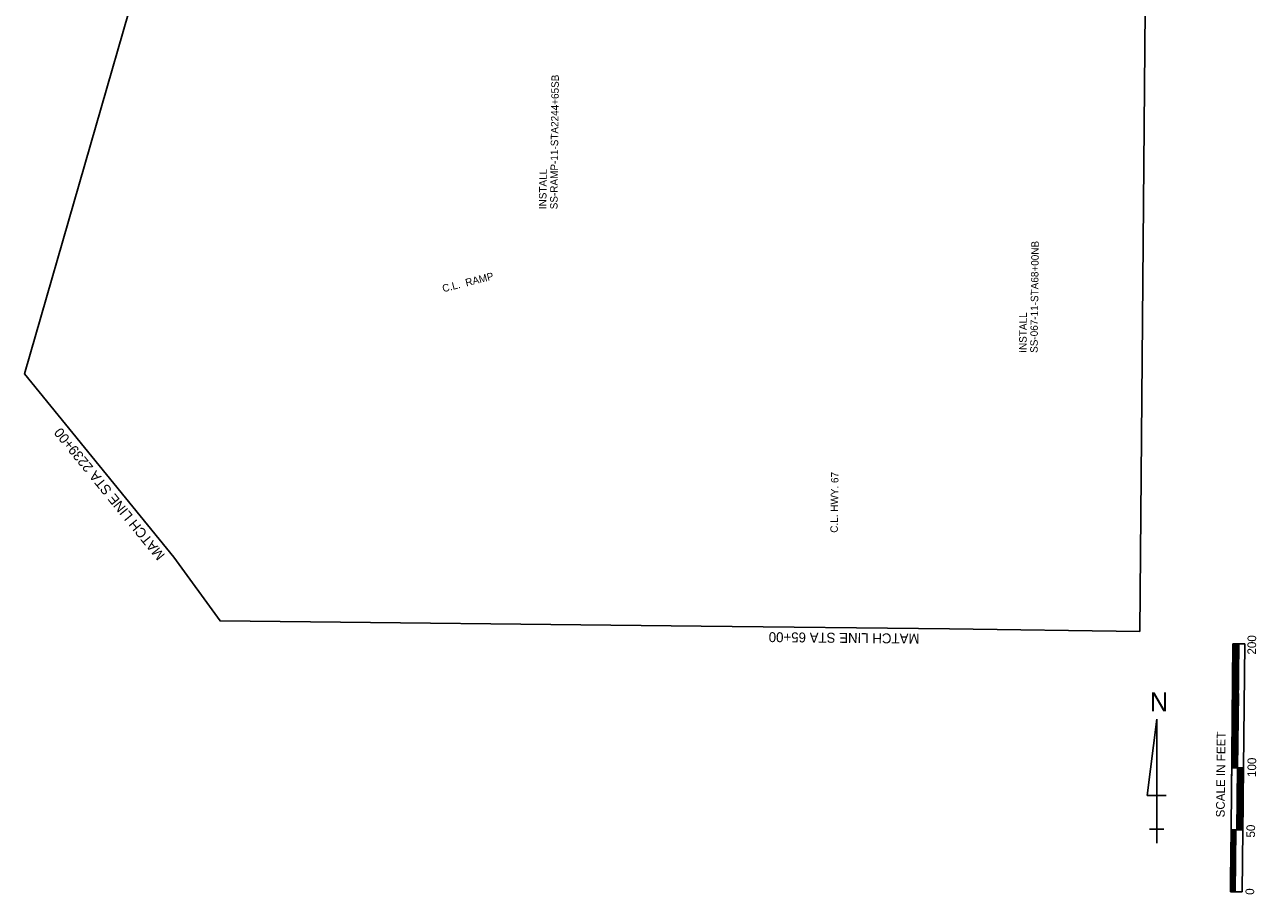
# Model space of a CAD drawing. Extents: x 1727679 to 1728713, y 772542 to 774073.
# Drawn here: x 1727679 to 1728672, y 772542 to 773243 of the extents above; entities that cross this region are included whole.
import ezdxf

# ---------------------------------------------------------------- set-up
doc = ezdxf.new("R2010")
doc.units = 0
for name, color, linetype in [('R_6IN_DASHED-RPM_WHITE_ENHANCED THERMO', 7, 'Continuous'), ('R_8IN_SOLID_WHITE_THERMO', 7, 'Continuous'), ('R_8IN_SOLID_YELLOW_THERMO', 7, 'Continuous'), ('R_PM_DOTTED_LINE', 7, 'Continuous'), ('R_RPM_TYPE 2_RED-WHITE', 7, 'Continuous'), ('R_WORDS_WHITE_THERMO', 7, 'Continuous')]:
    doc.layers.add(name, color=color, linetype=linetype)

msp = doc.modelspace()

# ---------------------------------------------------------------- linework, layer by layer
at = {"layer": 'R_8IN_SOLID_WHITE_THERMO'}
for p, q in [((1727799.51, 772813.62), (1727679.22, 772961.26)), ((1728224.75, 772757.78), (1728424.74, 772755.68))]:
    msp.add_line(p, q, dxfattribs=at)
at = {"layer": 'R_8IN_SOLID_YELLOW_THERMO'}
for p, q in [((1728652.14, 772623.66), (1728653.4, 772743.65)), ((1728653.15, 772643.65), (1728654.2, 772743.65)), ((1728663.02, 772743.55), (1728653.42, 772743.65)), ((1728653.95, 772643.64), (1728655, 772743.64)), ((1728654.75, 772643.63), (1728655.8, 772743.63)), ((1728655.55, 772643.63), (1728656.6, 772743.62)), ((1728656.35, 772643.62), (1728657.4, 772743.61)), ((1728657.15, 772643.61), (1728658.2, 772743.6)), ((1728660.9, 772543.56), (1728663, 772743.55)), ((1728651.31, 772543.66), (1728652.98, 772703.65)), ((1728657.15, 772643.61), (1728657.78, 772703.6)), ((1728661.96, 772643.56), (1728652.36, 772643.66)), ((1728656.63, 772593.61), (1728657.15, 772643.61)), ((1728657.43, 772593.6), (1728657.95, 772643.6)), ((1728658.23, 772593.59), (1728658.75, 772643.59)), ((1728659.03, 772593.59), (1728659.55, 772643.58)), ((1728659.83, 772593.58), (1728660.35, 772643.57)), ((1728660.63, 772593.57), (1728661.15, 772643.57)), ((1728661.32, 772583.56), (1728661.74, 772623.56)), ((1728661.43, 772593.56), (1728651.83, 772593.66)), ((1728652.11, 772543.66), (1728652.63, 772593.65)), ((1728652.9, 772543.65), (1728653.43, 772593.65)), ((1728653.71, 772543.64), (1728654.22, 772593.64)), ((1728654.51, 772543.63), (1728655.03, 772593.63)), ((1728655.31, 772543.62), (1728655.82, 772593.62)), ((1728651.31, 772543.66), (1728651.72, 772583.66)), ((1728660.9, 772543.56), (1728651.31, 772543.66))]:
    msp.add_line(p, q, dxfattribs=at)
at = {"layer": 'R_PM_DOTTED_LINE'}
for p, q in [((1728591.95, 772682.75), (1728584.26, 772621.21)), ((1728591.95, 772582.75), (1728591.95, 772682.75)), ((1728591.95, 772682.75), (1728591.95, 772605.83)), ((1728584.26, 772621.21), (1728599.65, 772621.21)), ((1728591.95, 772582.75), (1728591.95, 772605.83)), ((1728591.95, 772594.29), (1728586.19, 772594.29)), ((1728586.19, 772594.29), (1728597.72, 772594.29)), ((1728591.95, 772582.75), (1728591.95, 772594.29))]:
    msp.add_line(p, q, dxfattribs=at)
at = {"layer": 'R_RPM_TYPE 2_RED-WHITE'}
msp.add_lwpolyline([(1728578.21, 772753.58), (1728424.74, 772755.68), (1728224.75, 772757.78), (1727836.83, 772762.16), (1727799.51, 772813.62), (1727679.22, 772961.26), (1727776.45, 773299.36), (1728095.76, 773296.01), (1728101.38, 774009.49), (1728208.64, 774011.82), (1728353.95, 774013.76), (1728589.12, 774007.84)], close=True, dxfattribs=at)

# ---------------------------------------------------------------- texts
at = {"layer": 'R_6IN_DASHED-RPM_WHITE_ENHANCED THERMO'}
for s, rotation, p in [('C.L.  RAMP', 14.25227, (1728016.79, 773027.11)), ('C.L. HWY. 67', 89.25227, (1728334.77, 772833.15))]:
    msp.add_text(s, height=6, rotation=rotation, dxfattribs=at).set_placement(p)
at = {"layer": 'R_8IN_SOLID_WHITE_THERMO'}
for s, rotation, p in [('MATCH LINE STA 2239+00', 129.17051, (1727792.81, 772815.21)), ('MATCH LINE STA 65+00', 179.4, (1728400.74, 772751.77))]:
    msp.add_text(s, height=8, rotation=rotation, dxfattribs=at).set_placement(p)
at = {"layer": 'R_8IN_SOLID_YELLOW_THERMO'}
for s, height, p in [('200', 7.001, (1728672, 772734.93)), ('SCALE IN FEET', 7.0007, (1728646.7, 772603.64)), ('100', 7.001, (1728672.02, 772636.18)), ('50', 7.001, (1728671.16, 772587.37)), ('0', 7, (1728670.49, 772541.19))]:
    msp.add_text(s, height=height, rotation=89.40027, dxfattribs=at).set_placement(p)
at = {"layer": 'R_PM_DOTTED_LINE'}
msp.add_text('N', height=15.38, rotation=360, dxfattribs=at).set_placement((1728586.32, 772689.16))
at = {"layer": 'R_WORDS_WHITE_THERMO'}
for s, p in [('SS-RAMP-11-STA2244+65SB', (1728108.83, 773094.03)), ('INSTALL', (1728099.83, 773094.12)), ('SS-067-11-STA68+00NB', (1728495.93, 772978.23)), ('INSTALL', (1728486.93, 772978.32))]:
    msp.add_text(s, height=6, rotation=89.4, dxfattribs=at).set_placement(p)

doc.saveas('drawing.dxf')
